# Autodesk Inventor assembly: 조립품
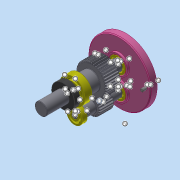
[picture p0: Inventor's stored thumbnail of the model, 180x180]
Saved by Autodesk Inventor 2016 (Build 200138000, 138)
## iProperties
Created: 2020-08
Part Number: 조립품
Material: 일반
Document SubType Name: Assembly
Designer: User
Author: User
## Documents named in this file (10)
- C:\Users\User\Desktop\700815V1002\조립품.iam
- C:\Users\User\Desktop\700815V1002\메인 축.ipt
- C:\Users\User\Desktop\700815V1002\베어링 608.ipt
- C:\Users\User\Desktop\700815V1002\베어링 6003.ipt
- C:\Users\User\Desktop\700815V1002\본체.ipt
- C:\Users\User\Desktop\700815V1002\볼트 M4.ipt
- C:\Users\User\Desktop\700815V1002\서브 축.ipt
- C:\Users\User\Desktop\700815V1002\오일 실 8 22 7.ipt
- C:\Users\User\Desktop\700815V1002\오일 실 17 32 8.ipt
- C:\Users\User\Desktop\700815V1002\커버.ipt
